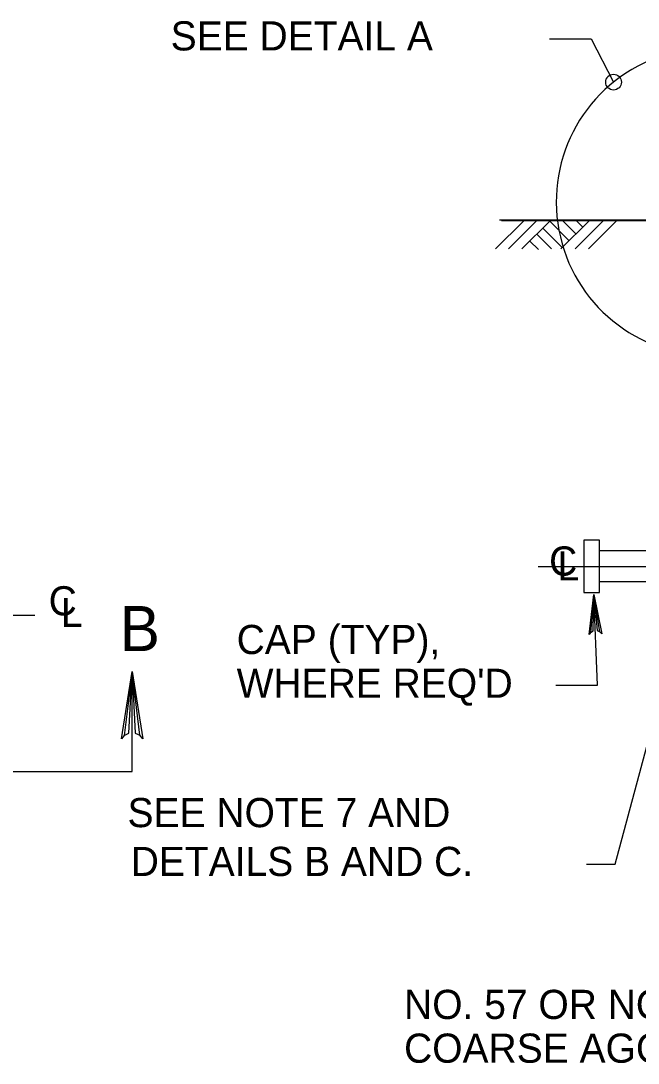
# Model space of a CAD drawing. Extents: x 638447 to 639352, y 298406 to 299000.
# Drawn here: x 638649.1 to 638720.2, y 298674.8 to 298794.8 of the extents above; entities that cross this region are included whole.
import ezdxf

# ---------------------------------------------------------------- set-up
doc = ezdxf.new("R2010")
doc.units = 0
for name, color, linetype in [('1', 7, 'Continuous'), ('2', 7, 'Continuous'), ('3', 7, 'Continuous')]:
    doc.layers.add(name, color=color, linetype=linetype)

msp = doc.modelspace()

# ---------------------------------------------------------------- linework, layer by layer
at = {"layer": '1'}
msp.add_circle((638717.393591, 298787.791488), 0.910672, dxfattribs=at)
at = {"layer": '2'}
for p, q in [((638703.782375, 298768.564), (638706.996375, 298771.778)), ((638721.880375, 298771.898), (638704.232375, 298771.898)), ((638705.286375, 298768.564), (638708.518375, 298771.796)), ((638706.840375, 298768.564), (638710.072375, 298771.796)), ((638710.004375, 298771.796), (638712.284375, 298769.514)), ((638711.316375, 298768.564), (638714.566375, 298771.814)), ((638711.558375, 298771.796), (638713.044375, 298770.31)), ((638712.958375, 298768.564), (638716.154375, 298771.762)), ((638713.130375, 298771.796), (638713.840375, 298771.088)), ((638714.514375, 298768.564), (638717.710375, 298771.762)), ((638709.226375, 298770.95), (638711.454375, 298768.72)), ((638707.756375, 298769.48), (638708.724375, 298768.512)), ((638708.534375, 298770.258), (638710.228375, 298768.564)), ((638721.754375, 298733.804), (638715.754375, 298733.804)), ((638718.754375, 298733.804), (638715.754375, 298733.804)), ((638708.694375, 298732.004), (638808.624375, 298732.004)), ((638721.754375, 298730.204), (638715.754375, 298730.204)), ((638650.717125, 298726.354), (638565.631125, 298726.354)), ((638661.929375, 298708.386), (638661.929375, 298719.8895)), ((638625.925375, 298708.386), (638661.929375, 298708.386))]:
    msp.add_line(p, q, dxfattribs=at)
for points in [[(638710.020375, 298792.788), (638714.820375, 298792.788), (638717.393625, 298787.7915)], [(638704.492375, 298771.844), (638721.768375, 298771.844)], [(638714.282375, 298697.684), (638717.588375, 298697.684), (638726.312375, 298730.088)], [(638710.746375, 298718.306), (638715.546375, 298718.306), (638715.110375, 298728.78)], [(638714.746375, 298724.402), (638715.054375, 298724.576), (638715.110375, 298728.78), (638714.746375, 298724.402), (638714.564375, 298724.17), (638715.110375, 298728.78), (638715.492375, 298724.598), (638715.810375, 298724.458), (638715.110375, 298728.78), (638716.028375, 298724.232), (638715.810375, 298724.458)], [(638661.003125, 298712.52475), (638661.537125, 298712.7985), (638661.929375, 298719.8895), (638661.003125, 298712.52475), (638660.682125, 298712.14625), (638661.929375, 298719.8895), (638662.280875, 298712.80175), (638662.808375, 298712.545), (638661.929375, 298719.8895), (638663.159625, 298712.14625), (638662.808375, 298712.545)]]:
    msp.add_lwpolyline(points, dxfattribs=at)
msp.add_lwpolyline([(638715.754375, 298729.004), (638715.754375, 298735.004), (638713.954375, 298735.004), (638713.954375, 298729.004)], close=True, dxfattribs=at)
msp.add_arc((638728.491221, 298774.003748), 17.699271, 110.26046667, 71.742925, dxfattribs=at)

# ---------------------------------------------------------------- texts
at = {"layer": '3'}
for s, height, p in [('SEE DETAIL A', 3.36, (638666.361375, 298791.438)), ('C', 3.359988, (638709.962375, 298730.94)), ('L', 3.359988, (638710.940375, 298730.376)), ('C', 3.359988, (638652.299875, 298726.3535)), ('L', 3.359988, (638653.711125, 298725.014)), ('B', 5.2, (638660.487375, 298722.23425)), ('CAP (TYP),', 3.36, (638673.964375, 298721.898)), ("WHERE REQ'D", 3.36, (638673.964375, 298716.858)), ('SEE NOTE 7 AND', 3.359988, (638661.390125, 298701.958)), ('DETAILS B AND C.', 3.36, (638661.758125, 298696.33)), ('NO. 57 OR NO. 67', 3.359988, (638693.252375, 298679.858)), ('COARSE AGGREGATE', 3.359988, (638693.252375, 298674.818))]:
    msp.add_text(s, height=height, dxfattribs=at).set_placement(p)

doc.saveas('drawing.dxf')
